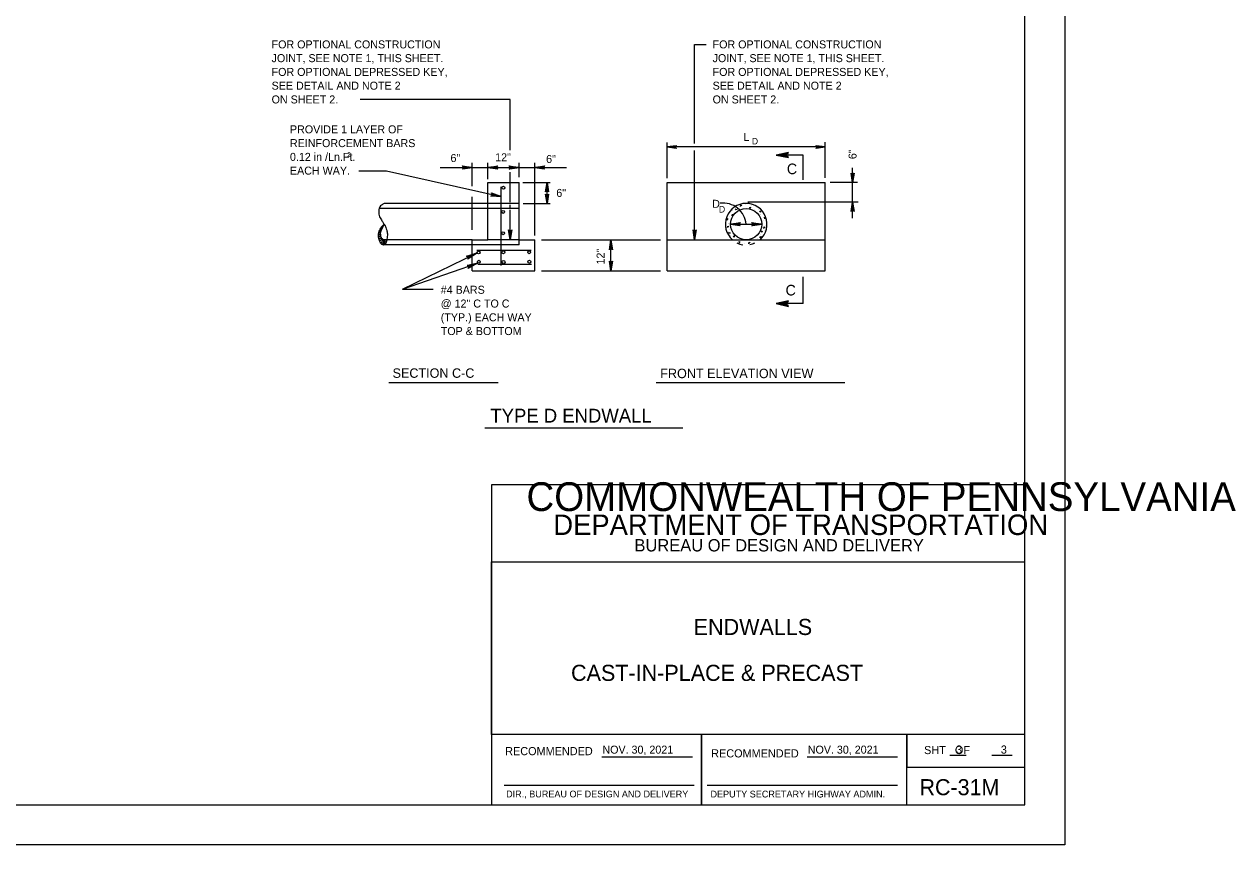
# Model space of a CAD drawing. Extents: x 638877 to 639960, y 297341 to 299123.
# Drawn here: x 639328 to 639782.3, y 297341.3 to 297649 of the extents above; entities that cross this region are included whole.
import ezdxf

# ---------------------------------------------------------------- set-up
doc = ezdxf.new("R2010")
doc.units = 0
for name, color, linetype in [('1', 7, 'Continuous'), ('2', 7, 'Continuous'), ('3', 7, 'Continuous'), ('PLT-BNDY', 7, 'Continuous')]:
    doc.layers.add(name, color=color, linetype=linetype)

msp = doc.modelspace()

# ---------------------------------------------------------------- linework, layer by layer
at = {"layer": '1'}
for p, q in [((639703.19, 297356.28), (639703.19, 297920.28)), ((639579.39, 297604.22), (639579.39, 297641.38)), ((639510.24, 297601.8), (639510.24, 297620.75)), ((639579.39, 297568.13), (639579.39, 297601.64)), ((639620.12, 297590.59), (639620.12, 297599.9)), ((639510.24, 297582.2), (639510.24, 297593.47)), ((639510.24, 297580.21), (639510.24, 297581.23)), ((639510.24, 297568.13), (639510.24, 297579.4)), ((639620.12, 297544.21), (639620.12, 297554.23)), ((639703.19, 297476.28), (639503.19, 297476.28)), ((639503.19, 297476.28), (639503.19, 297356.28)), ((639703.19, 297447.32), (639703.19, 297476.28)), ((639503.19, 297382.64), (639503.19, 297447.32)), ((639503.19, 297447.32), (639703.19, 297447.32)), ((639703.19, 297382.64), (639503.19, 297382.64)), ((639581.99, 297356.28), (639581.99, 297382.64)), ((639581.99, 297382.64), (639581.99, 297356.28)), ((639658.99, 297356.28), (639658.99, 297382.64)), ((639658.99, 297382.64), (639658.99, 297370.33)), ((639703.19, 297356.28), (639703.19, 297382.64)), ((639544.65, 297374.27), (639578.54, 297374.27)), ((639621.65, 297374.27), (639655.52, 297374.27)), ((639675.05, 297374.82), (639681.2, 297374.82)), ((639690.86, 297374.82), (639698.51, 297374.82)), ((639658.99, 297370.33), (639703.19, 297370.33)), ((639507.95, 297363.61), (639579.2, 297363.61)), ((639584.12, 297363.61), (639655.46, 297363.61)), ((638917.19, 297356.28), (639703.19, 297356.28))]:
    msp.add_line(p, q, dxfattribs=at)
for centre in [(639507.67, 297587.64), (639507.59, 297578.6), (639507.59, 297570.6), (639498.39, 297563.4), (639507.67, 297563.48), (639517.35, 297563.48), (639498.47, 297559.88), (639507.75, 297559.8), (639517.43, 297559.88)]:
    msp.add_circle(centre, 0.554, dxfattribs=at)
msp.add_arc((639590.03, 297573.2), 8.72, 5.0952, 96.7352, dxfattribs=at)
at = {"layer": '2'}
for p, q in [((639579.39, 297641.38), (639583.67, 297641.38)), ((639510.24, 297620.75), (639454.03, 297620.75)), ((639569.14, 297591.24), (639569.14, 297604.62)), ((639628.29, 297591.34), (639628.29, 297604.78)), ((639628.29, 297602.93), (639569.14, 297602.93)), ((639620.12, 297599.9), (639609.97, 297599.9)), ((639484.04, 297595.22), (639501.88, 297595.22)), ((639496.03, 297588.2), (639496.03, 297596.94)), ((639501.88, 297590.9), (639501.88, 297596.94)), ((639501.94, 297595.22), (639513.64, 297595.22)), ((639513.58, 297591.6), (639513.58, 297596.94)), ((639513.58, 297595.22), (639531.41, 297595.22)), ((639519.43, 297569.74), (639519.43, 297596.94)), ((639638.65, 297589.58), (639638.65, 297595.15)), ((639453.52, 297593.97), (639463.82, 297593.97)), ((639463.82, 297593.97), (639506.91, 297584.4)), ((639501.88, 297568.13), (639501.88, 297589.58)), ((639501.88, 297589.58), (639513.58, 297589.58)), ((639513.58, 297566.18), (639513.58, 297589.58)), ((639514.93, 297589.58), (639525.28, 297589.58)), ((639524.05, 297581.77), (639524.05, 297589.58)), ((639569.14, 297556.43), (639569.14, 297589.58)), ((639569.14, 297589.58), (639628.29, 297589.58)), ((639628.29, 297556.43), (639628.29, 297589.58)), ((639640.44, 297589.58), (639630.2, 297589.58)), ((639638.65, 297576.3), (639638.65, 297589.58)), ((639506.91, 297558.44), (639506.91, 297588)), ((639501.88, 297581.78), (639462.98, 297581.78)), ((639496.03, 297571.9), (639496.03, 297584.19)), ((639513.58, 297581.78), (639501.88, 297581.78)), ((639515.12, 297581.78), (639525.28, 297581.78)), ((639640.72, 297582.28), (639599.36, 297582.28)), ((639513.58, 297579.83), (639461.23, 297579.83)), ((639592.79, 297573.98), (639604.57, 297573.98)), ((639598.72, 297573.98), (639598.72, 297573.98)), ((639496.03, 297568.13), (639464, 297568.13)), ((639496.03, 297556.43), (639496.03, 297568.13)), ((639496.03, 297568.13), (639501.88, 297568.13)), ((639513.58, 297568.13), (639501.88, 297568.13)), ((639513.58, 297568.13), (639519.43, 297568.13)), ((639519.43, 297556.43), (639519.43, 297568.13)), ((639522.03, 297568.13), (639566.54, 297568.13)), ((639548.03, 297556.43), (639548.03, 297568.13)), ((639569.14, 297568.13), (639628.29, 297568.13)), ((639598.72, 297568.13), (639604.57, 297568.13)), ((639496.03, 297566.18), (639462.98, 297566.18)), ((639469.87, 297549.67), (639497.6, 297563.09)), ((639513.58, 297566.18), (639496.03, 297566.18)), ((639497.75, 297564.29), (639518.04, 297564.29)), ((639469.87, 297549.67), (639497.92, 297559.32)), ((639498.07, 297559.02), (639518.28, 297559.02)), ((639496.03, 297556.43), (639519.43, 297556.43)), ((639522.03, 297556.43), (639566.54, 297556.43)), ((639569.14, 297556.43), (639628.29, 297556.43)), ((639469.87, 297549.67), (639481.3, 297549.67)), ((639620.12, 297544.21), (639609.97, 297544.21))]:
    msp.add_line(p, q, dxfattribs=at)
for points in [[(639572.45, 297602.51), (639572.33, 297602.75), (639569.14, 297602.93), (639572.45, 297602.51), (639572.62, 297602.37), (639569.14, 297602.93), (639572.32, 297603.09), (639572.44, 297603.32), (639569.14, 297602.93), (639572.62, 297603.48), (639572.44, 297603.32)], [(639624.99, 297603.35), (639625.11, 297603.11), (639628.29, 297602.93), (639624.99, 297603.35), (639624.82, 297603.49), (639628.29, 297602.93), (639625.11, 297602.77), (639625, 297602.53), (639628.29, 297602.93), (639624.82, 297602.38), (639625, 297602.53)], [(639614.34, 297600.63), (639614.17, 297600.21), (639609.97, 297599.9), (639614.34, 297600.63), (639614.56, 297600.88), (639609.97, 297599.9), (639614.17, 297599.62), (639614.32, 297599.21), (639609.97, 297599.9), (639614.56, 297598.93), (639614.32, 297599.21)], [(639492.48, 297595.67), (639492.62, 297595.41), (639496.03, 297595.22), (639492.48, 297595.67), (639492.3, 297595.82), (639496.03, 297595.22), (639492.62, 297595.06), (639492.49, 297594.8), (639496.03, 297595.22), (639492.3, 297594.63), (639492.49, 297594.8)], [(639505.42, 297594.78), (639505.28, 297595.04), (639501.88, 297595.22), (639505.42, 297594.78), (639505.6, 297594.62), (639501.88, 297595.22), (639505.28, 297595.39), (639505.41, 297595.65), (639501.88, 297595.22), (639505.6, 297595.82), (639505.41, 297595.65)], [(639510.03, 297595.67), (639510.17, 297595.41), (639513.58, 297595.22), (639510.03, 297595.67), (639509.85, 297595.82), (639513.58, 297595.22), (639510.17, 297595.06), (639510.04, 297594.8), (639513.58, 297595.22), (639509.85, 297594.63), (639510.04, 297594.8)], [(639522.97, 297594.78), (639522.83, 297595.04), (639519.43, 297595.22), (639522.97, 297594.78), (639523.15, 297594.62), (639519.43, 297595.22), (639522.83, 297595.39), (639522.96, 297595.65), (639519.43, 297595.22), (639523.15, 297595.82), (639522.96, 297595.65)], [(639523.64, 297586.27), (639523.88, 297586.39), (639524.05, 297589.58), (639523.64, 297586.27), (639523.49, 297586.1), (639524.05, 297589.58), (639524.21, 297586.4), (639524.45, 297586.28), (639524.05, 297589.58), (639524.6, 297586.1), (639524.45, 297586.28)], [(639639.02, 297592.93), (639638.78, 297592.81), (639638.61, 297589.63), (639639.02, 297592.93), (639639.17, 297593.1), (639638.61, 297589.63), (639638.45, 297592.81), (639638.21, 297592.92), (639638.61, 297589.63), (639638.06, 297593.1), (639638.21, 297592.92)], [(639503.34, 297585.52), (639503.43, 297585.23), (639506.91, 297584.4), (639503.34, 297585.52), (639503.19, 297585.71), (639506.91, 297584.4), (639503.37, 297584.86), (639503.19, 297584.63), (639506.91, 297584.4), (639502.96, 297584.49), (639503.19, 297584.63)], [(639524.47, 297585.08), (639524.23, 297584.96), (639524.05, 297581.77), (639524.47, 297585.08), (639524.61, 297585.25), (639524.05, 297581.77), (639523.9, 297584.95), (639523.66, 297585.07), (639524.05, 297581.77), (639523.5, 297585.25), (639523.66, 297585.07)], [(639596.6, 297580.63), (639596.75, 297581.19), (639597.04, 297580.81)], [(639638.23, 297578.98), (639638.47, 297579.1), (639638.65, 297582.28), (639638.23, 297578.98), (639638.09, 297578.8), (639638.65, 297582.28), (639638.8, 297579.1), (639639.04, 297578.98), (639638.65, 297582.28), (639639.2, 297578.8), (639639.04, 297578.98)], [(639591.7, 297575.5), (639591.55, 297576.06), (639592, 297575.88)], [(639593.59, 297577.71), (639593.54, 297577.12), (639593.18, 297577.45)], [(639595.31, 297579.43), (639594.73, 297579.38), (639594.99, 297579.79)], [(639600.22, 297579.82), (639600.08, 297580.38), (639600.52, 297580.2)], [(639604.19, 297579.13), (639604.13, 297578.55), (639603.78, 297578.87)], [(639605.7, 297576.03), (639605.55, 297576.59), (639606, 297576.41)], [(639510.68, 297571.67), (639510.43, 297571.53), (639510.24, 297568.13), (639510.68, 297571.67), (639510.84, 297571.85), (639510.24, 297568.13), (639510.07, 297571.53), (639509.82, 297571.66), (639510.24, 297568.13), (639509.65, 297571.85), (639509.82, 297571.66)], [(639579.84, 297571.67), (639579.58, 297571.53), (639579.39, 297568.13), (639579.84, 297571.67), (639579.99, 297571.85), (639579.39, 297568.13), (639579.23, 297571.53), (639578.97, 297571.66), (639579.39, 297568.13), (639578.8, 297571.85), (639578.97, 297571.66)], [(639591.67, 297572.71), (639591.82, 297573.27), (639592.12, 297572.89)], [(639596.33, 297573.53), (639596.19, 297573.79), (639592.79, 297573.98), (639596.33, 297573.53), (639596.51, 297573.38), (639592.79, 297573.98), (639596.19, 297574.14), (639596.32, 297574.4), (639592.79, 297573.98), (639596.51, 297574.57), (639596.32, 297574.4)], [(639601.03, 297574.42), (639601.16, 297574.16), (639604.57, 297573.98), (639601.03, 297574.42), (639600.85, 297574.58), (639604.57, 297573.98), (639601.16, 297573.81), (639601.04, 297573.55), (639604.57, 297573.98), (639600.85, 297573.38), (639601.04, 297573.55)], [(639604.54, 297570.91), (639604.4, 297571.47), (639604.84, 297571.29)], [(639605.31, 297572.42), (639605.46, 297572.98), (639605.76, 297572.6)], [(639547.58, 297564.58), (639547.84, 297564.72), (639548.03, 297568.13), (639547.58, 297564.58), (639547.42, 297564.4), (639548.03, 297568.13), (639548.19, 297564.72), (639548.45, 297564.6), (639548.03, 297568.13), (639548.62, 297564.4), (639548.45, 297564.6)], [(639592.8, 297570.67), (639592.22, 297570.62), (639592.48, 297571.02)], [(639594.26, 297569.7), (639594.21, 297569.11), (639593.86, 297569.44)], [(639596.19, 297566.88), (639596.04, 297567.44), (639596.49, 297567.26)], [(639599.69, 297566.65), (639599.84, 297567.21), (639600.14, 297566.83)], [(639604.19, 297569.43), (639604.13, 297568.85), (639603.78, 297569.17)], [(639494.06, 297561.9), (639494.3, 297561.71), (639497.6, 297563.09), (639494.06, 297561.9), (639493.82, 297561.96), (639497.6, 297563.09), (639494.47, 297561.38), (639494.47, 297561.08), (639497.6, 297563.09), (639494.36, 297560.84), (639494.47, 297561.08)], [(639494.29, 297558.44), (639494.51, 297558.23), (639497.92, 297559.32), (639494.29, 297558.44), (639494.05, 297558.52), (639497.92, 297559.32), (639494.64, 297557.88), (639494.62, 297557.59), (639497.92, 297559.32), (639494.49, 297557.35), (639494.62, 297557.59)], [(639548.47, 297559.97), (639548.21, 297559.83), (639548.03, 297556.43), (639548.47, 297559.97), (639548.63, 297560.15), (639548.03, 297556.43), (639547.86, 297559.83), (639547.6, 297559.96), (639548.03, 297556.43), (639547.43, 297560.15), (639547.6, 297559.96)], [(639614.34, 297545.01), (639614.17, 297544.55), (639609.97, 297544.21), (639614.34, 297545.01), (639614.56, 297545.29), (639609.97, 297544.21), (639614.17, 297543.9), (639614.32, 297543.45), (639609.97, 297544.21), (639614.56, 297543.14), (639614.32, 297543.45)]]:
    msp.add_lwpolyline(points, dxfattribs=at)
msp.add_circle((639598.72, 297573.98), 5.85, dxfattribs=at)
for centre, radius, start, end in [((639598.72, 297573.98), 7.8, 311.7101, 228.5196), ((639461.53, 297571.51), 0.253, 127.1633, 351.4543), ((639461.79, 297572.09), 0.174, 136.1947, 336.6659), ((639462.12, 297572.62), 0.173, 146.1449, 344.2438), ((639462.51, 297573.24), 0.298, 214.194, 254.3926), ((639462.61, 297573.37), 0.127, 86.947, 3.053), ((639461.28, 297569.71), 0.359, 191.4984, 340.2996), ((639461.33, 297570.43), 0.315, 193.3175, 327.589), ((639461.4, 297569.05), 0.415, 204.5127, 8.9205), ((639461.45, 297571.01), 0.291, 177.6701, 316.2915), ((639461.36, 297568.56), 0.667, 261.4216, 6.7911), ((639461.21, 297568.02), 1.18, 297.4769, 15.1492), ((639461.71, 297567.64), 1.18, 294.0664, 21.1035), ((639461.7, 297567.67), 1.67, 302.4871, 11.509), ((639598.62, 297573.98), 7.8, 244.3688, 261.4786), ((639598.62, 297573.98), 7.8, 280.9572, 295.3267)]:
    msp.add_arc(centre, radius, start, end, dxfattribs=at)
for points in [[(639462.98, 297581.78), (639462.47, 297581.43), (639461.95, 297581.1), (639461.38, 297580.46), (639461.02, 297579.5), (639461, 297577.71), (639461.28, 297576.74), (639461.73, 297576.02), (639462.14, 297575.26), (639462.45, 297574.74), (639462.71, 297574.29), (639462.98, 297573.98), (639463.38, 297573.38), (639463.62, 297572.76), (639463.93, 297571.74), (639464.07, 297571.12), (639464.19, 297570.38), (639464.19, 297569.83), (639464.12, 297568.9), (639463.93, 297567.93), (639463.76, 297567.21), (639463.4, 297566.47), (639462.98, 297566.18), (639462.43, 297566.21), (639461.9, 297566.66), (639461.47, 297567.19), (639461.19, 297567.81), (639460.95, 297568.62), (639460.88, 297569.59), (639460.9, 297570.4), (639461.16, 297571.4), (639461.54, 297572.14), (639461.9, 297572.81), (639462.35, 297573.33), (639462.98, 297573.98)], [(639464, 297568.13), (639463.52, 297568.09), (639462.9, 297568.14), (639462.57, 297568.19), (639462.31, 297568.43), (639462.12, 297568.62), (639461.92, 297568.93), (639461.78, 297569.36), (639461.69, 297569.81), (639461.66, 297570.31), (639461.66, 297570.74), (639461.76, 297571.19), (639461.85, 297571.62), (639462.02, 297571.93), (639462.33, 297572.48), (639462.43, 297572.74), (639462.52, 297572.97), (639462.78, 297573.38), (639462.9, 297573.67), (639462.98, 297573.98)]]:
    msp.add_spline(points, degree=3, dxfattribs=at)
at = {"layer": '3'}
for p, q in [((639464.73, 297514.62), (639505.74, 297514.62)), ((639564.99, 297514.62), (639635.7, 297514.62)), ((639500.74, 297497.64), (639574.98, 297497.64))]:
    msp.add_line(p, q, dxfattribs=at)
at = {"layer": 'PLT-BNDY'}
msp.add_lwpolyline([(638877.19, 297935.28), (639718.19, 297935.28), (639718.19, 297341.28), (638877.19, 297341.28)], close=True, dxfattribs=at)

# ---------------------------------------------------------------- texts
at = {"layer": '1'}
for s, height, p in [('D', 2.43, (639600.85, 297603.9)), ('2', 1.8, (639449.09, 297599.2)), ('D', 3, (639585.98, 297580.12)), ('D', 2.43, (639588.5, 297578.35)), ('COMMONWEALTH OF PENNSYLVANIA', 10.7834, (639516.34, 297466.43)), ('DEPARTMENT OF TRANSPORTATION', 7.6843, (639526.4, 297457.43)), ('BUREAU OF DESIGN AND DELIVERY', 4.6221, (639556.83, 297451.27)), ('ENDWALLS', 6.04, (639579.04, 297419.94)), ('CAST-IN-PLACE & PRECAST', 6.04, (639533.05, 297402.73)), ('RECOMMENDED', 3.048, (639508.35, 297374.88)), ('NOV. 30, 2021', 3, (639544.82, 297375.45)), ('RECOMMENDED', 3.048, (639585.6, 297374.04)), ('NOV. 30, 2021', 3, (639621.82, 297375.45)), ('SHT   OF', 3.048, (639665.44, 297375.28)), ('APPROVED', 0.0192, (639546.21, 297374.22)), ('RC-31M', 6.016, (639663.72, 297359.87)), ('DIR., BUREAU OF DESIGN AND DELIVERY', 2.54, (639508.7, 297359.05)), ('DEPUTY SECRETARY HIGHWAY ADMIN.', 2.54, (639585.34, 297359.02))]:
    msp.add_text(s, height=height, dxfattribs=at).set_placement(p)
at = {"layer": '2'}
for p in [(639598.4, 297581.14), (639600.67, 297581), (639592.32, 297576.72), (639593.48, 297578.92), (639595.91, 297579.67), (639601.59, 297579.55), (639603.13, 297579.5), (639603.98, 297577.42), (639592.08, 297574.19), (639592.39, 297571.9), (639605.11, 297575.23), (639605.35, 297571.39), (639605.91, 297573.49), (639592.82, 297569.56), (639594.97, 297568.52), (639597.99, 297566.68), (639601.13, 297567.12), (639602.63, 297568.52), (639603.93, 297570.16)]:
    msp.add_text('.', height=0.976, rotation=10.0975, dxfattribs=at).set_placement(p)
for p in [(639677.39, 297375.49), (639694.21, 297375.47)]:
    msp.add_text('3', height=3.05, dxfattribs=at).set_placement(p)
at = {"layer": '3'}
for s, height, p in [('FOR OPTIONAL CONSTRUCTION', 2.9999, (639420.77, 297639.9)), ('FOR OPTIONAL CONSTRUCTION', 2.9999, (639586.14, 297639.9)), ('JOINT, SEE NOTE 1, THIS SHEET.', 2.9999, (639420.77, 297634.74)), ('JOINT, SEE NOTE 1, THIS SHEET.', 2.9999, (639586.14, 297634.74)), ('FOR OPTIONAL DEPRESSED KEY,', 2.9999, (639420.77, 297629.58)), ('FOR OPTIONAL DEPRESSED KEY,', 2.9999, (639586.14, 297629.58)), ('SEE DETAIL AND NOTE 2 ', 2.9999, (639420.77, 297624.42)), ('SEE DETAIL AND NOTE 2 ', 2.9999, (639586.14, 297624.42)), ('ON SHEET 2.', 2.9999, (639420.77, 297619.26)), ('ON SHEET 2.', 2.9999, (639586.14, 297619.26)), ('PROVIDE 1 LAYER OF', 2.9999, (639427.65, 297608.04)), ('L', 3, (639597.74, 297605.18)), ('REINFORCEMENT BARS', 2.9999, (639427.65, 297602.88)), ('0.12 in /Ln.Ft. ', 2.9999, (639427.65, 297597.73)), ('EACH WAY.', 3, (639427.65, 297592.57)), ('C', 3.99, (639613.99, 297592.73)), ('6"', 3, (639527.53, 297584.21)), ('#4 BARS', 3, (639484.2, 297547.89)), ('C', 3.99, (639613.5, 297547.25)), ('@ 12" C TO C', 2.9999, (639484.2, 297542.73)), ('(TYP.) EACH WAY', 2.9999, (639484.2, 297537.57)), ('TOP & BOTTOM', 2.9999, (639484.2, 297532.41)), ('SECTION C-C', 3.5299, (639466.13, 297516.38)), ('FRONT ELEVATION VIEW', 3.5299, (639566.51, 297516.25)), ('TYPE D ENDWALL', 5.1858, (639502.8, 297499.59))]:
    msp.add_text(s, height=height, dxfattribs=at).set_placement(p)
for s, rotation, p in [('6"', 360, (639487.85, 297597.3)), ('12"', 360, (639504.61, 297597.57)), ('6"', 360, (639523.71, 297596.92)), ('6"', 90, (639640.12, 297598.38)), ('12"', 90, (639545.63, 297558.87))]:
    msp.add_text(s, height=3, rotation=rotation, dxfattribs=at).set_placement(p)

doc.saveas('drawing.dxf')
